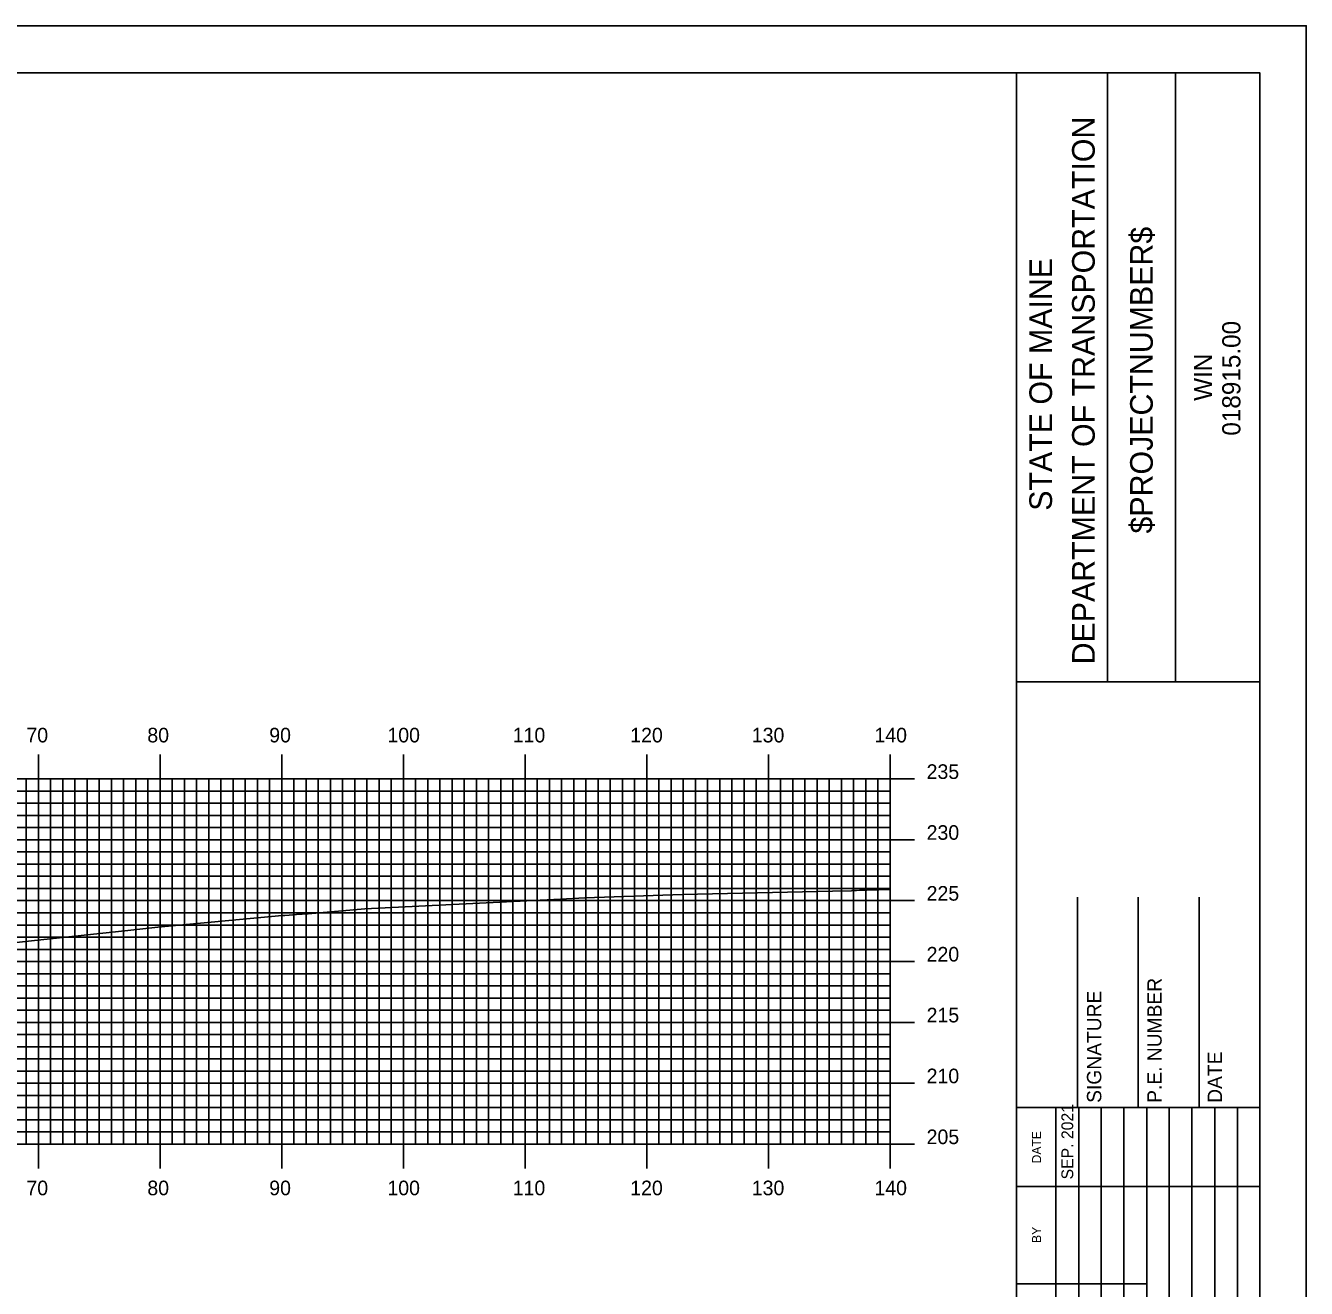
# Model space of a CAD drawing. Extents: x 851348 to 851692, y 364785 to 365005.
# Drawn here: x 851583.1 to 851688.4, y 364901.4 to 365005.1 of the extents above; entities that cross this region are included whole.
import ezdxf

# ---------------------------------------------------------------- set-up
doc = ezdxf.new("R2010")
doc.units = 0
for name, color, linetype in [('BORDER', 7, 'Continuous'), ('H_V ANNOTATION', 7, 'Continuous'), ('MAJOR', 7, 'Continuous'), ('MINOR', 7, 'Continuous'), ('PLOT BOUNDARY', 7, 'Continuous'), ('S_Roadway_Centerline', 7, 'Continuous')]:
    doc.layers.add(name, color=color, linetype=linetype)

msp = doc.modelspace()

# ---------------------------------------------------------------- linework, layer by layer
at = {"layer": 'BORDER'}
for p, q in [((851664.59, 364791.23), (851664.59, 365001.23)), ((851672.05, 364951.23), (851672.05, 365001.23)), ((851677.64, 364951.23), (851677.64, 365001.23)), ((851664.59, 364951.22), (851684.59, 364951.22)), ((851669.59, 364916.24), (851669.59, 364933.53)), ((851674.59, 364916.24), (851674.59, 364933.53)), ((851679.59, 364916.24), (851679.59, 364933.53)), ((851664.59, 364916.24), (851684.59, 364916.24))]:
    msp.add_line(p, q, dxfattribs=at)
msp.add_lwpolyline([(851364.59, 364791.23), (851684.59, 364791.23), (851684.59, 365001.23), (851364.59, 365001.23)], close=True, dxfattribs=at)
for points in [[(851667.82, 364909.74), (851667.82, 364916.24)], [(851669.69, 364881.24), (851669.69, 364916.24)], [(851671.55, 364916.24), (851671.55, 364881.24)], [(851673.41, 364881.24), (851673.41, 364916.24)], [(851675.28, 364881.24), (851675.28, 364916.24)], [(851677.14, 364881.24), (851677.14, 364916.24)], [(851679, 364881.24), (851679, 364916.24)], [(851680.87, 364881.24), (851680.87, 364916.24)], [(851682.73, 364881.24), (851682.73, 364916.24)], [(851667.82, 364881.24), (851667.82, 364914.83)], [(851664.59, 364909.74), (851684.59, 364909.74)], [(851664.59, 364901.74), (851667.82, 364901.74)], [(851667.82, 364901.74), (851675.27, 364901.74)]]:
    msp.add_lwpolyline(points, dxfattribs=at)
at = {"layer": 'MAJOR'}
for p, q in [((851584.19, 364945.24), (851584.19, 364943.23)), ((851594.19, 364945.24), (851594.19, 364943.23)), ((851604.19, 364945.24), (851604.19, 364943.23)), ((851614.19, 364945.24), (851614.19, 364943.23)), ((851624.19, 364945.24), (851624.19, 364943.23)), ((851634.19, 364945.24), (851634.19, 364943.23)), ((851644.19, 364945.24), (851644.19, 364943.23)), ((851654.19, 364945.24), (851654.19, 364943.23)), ((851514.19, 364943.23), (851654.19, 364943.23)), ((851514.19, 364943.23), (851654.19, 364943.23)), ((851584.19, 364913.23), (851584.19, 364943.23)), ((851594.19, 364913.23), (851594.19, 364943.23)), ((851604.19, 364913.23), (851604.19, 364943.23)), ((851614.19, 364913.23), (851614.19, 364943.23)), ((851624.19, 364913.23), (851624.19, 364943.23)), ((851634.19, 364913.23), (851634.19, 364943.23)), ((851644.19, 364913.23), (851644.19, 364943.23)), ((851656.2, 364943.23), (851652.19, 364943.23)), ((851654.19, 364913.23), (851654.19, 364943.23)), ((851654.19, 364913.23), (851654.19, 364943.23)), ((851514.19, 364938.23), (851654.19, 364938.23)), ((851656.2, 364938.23), (851652.19, 364938.23)), ((851514.19, 364933.23), (851654.19, 364933.23)), ((851656.2, 364933.23), (851652.19, 364933.23)), ((851514.19, 364928.23), (851654.19, 364928.23)), ((851656.2, 364928.23), (851652.19, 364928.23)), ((851514.19, 364923.23), (851654.19, 364923.23)), ((851656.2, 364923.23), (851652.19, 364923.23)), ((851514.19, 364918.23), (851654.19, 364918.23)), ((851656.2, 364918.23), (851652.19, 364918.23)), ((851514.19, 364913.23), (851654.19, 364913.23)), ((851514.19, 364913.23), (851654.19, 364913.23)), ((851584.19, 364911.23), (851584.19, 364913.23)), ((851594.19, 364911.23), (851594.19, 364913.23)), ((851604.19, 364911.23), (851604.19, 364913.23)), ((851614.19, 364911.23), (851614.19, 364913.23)), ((851624.19, 364911.23), (851624.19, 364913.23)), ((851634.19, 364911.23), (851634.19, 364913.23)), ((851644.19, 364911.23), (851644.19, 364913.23)), ((851656.2, 364913.23), (851652.19, 364913.23)), ((851654.19, 364911.23), (851654.19, 364913.23))]:
    msp.add_line(p, q, dxfattribs=at)
at = {"layer": 'MINOR'}
for p, q in [((851583.19, 364913.23), (851583.19, 364943.23)), ((851585.19, 364913.23), (851585.19, 364943.23)), ((851586.19, 364913.23), (851586.19, 364943.23)), ((851587.19, 364913.23), (851587.19, 364943.23)), ((851588.19, 364913.23), (851588.19, 364943.23)), ((851589.19, 364913.23), (851589.19, 364943.23)), ((851590.19, 364913.23), (851590.19, 364943.23)), ((851591.19, 364913.23), (851591.19, 364943.23)), ((851592.19, 364913.23), (851592.19, 364943.23)), ((851593.19, 364913.23), (851593.19, 364943.23)), ((851595.19, 364913.23), (851595.19, 364943.23)), ((851596.19, 364913.23), (851596.19, 364943.23)), ((851597.19, 364913.23), (851597.19, 364943.23)), ((851598.19, 364913.23), (851598.19, 364943.23)), ((851599.19, 364913.23), (851599.19, 364943.23)), ((851600.19, 364913.23), (851600.19, 364943.23)), ((851601.19, 364913.23), (851601.19, 364943.23)), ((851602.19, 364913.23), (851602.19, 364943.23)), ((851603.19, 364913.23), (851603.19, 364943.23)), ((851605.19, 364913.23), (851605.19, 364943.23)), ((851606.19, 364913.23), (851606.19, 364943.23)), ((851607.19, 364913.23), (851607.19, 364943.23)), ((851608.19, 364913.23), (851608.19, 364943.23)), ((851609.19, 364913.23), (851609.19, 364943.23)), ((851610.19, 364913.23), (851610.19, 364943.23)), ((851611.19, 364913.23), (851611.19, 364943.23)), ((851612.19, 364913.23), (851612.19, 364943.23)), ((851613.19, 364913.23), (851613.19, 364943.23)), ((851615.19, 364913.23), (851615.19, 364943.23)), ((851616.19, 364913.23), (851616.19, 364943.23)), ((851617.19, 364913.23), (851617.19, 364943.23)), ((851618.19, 364913.23), (851618.19, 364943.23)), ((851619.19, 364913.23), (851619.19, 364943.23)), ((851620.19, 364913.23), (851620.19, 364943.23)), ((851621.19, 364913.23), (851621.19, 364943.23)), ((851622.19, 364913.23), (851622.19, 364943.23)), ((851623.19, 364913.23), (851623.19, 364943.23)), ((851625.19, 364913.23), (851625.19, 364943.23)), ((851626.19, 364913.23), (851626.19, 364943.23)), ((851627.19, 364913.23), (851627.19, 364943.23)), ((851628.19, 364913.23), (851628.19, 364943.23)), ((851629.19, 364913.23), (851629.19, 364943.23)), ((851630.19, 364913.23), (851630.19, 364943.23)), ((851631.19, 364913.23), (851631.19, 364943.23)), ((851632.19, 364913.23), (851632.19, 364943.23)), ((851633.19, 364913.23), (851633.19, 364943.23)), ((851635.19, 364913.23), (851635.19, 364943.23)), ((851636.19, 364913.23), (851636.19, 364943.23)), ((851637.19, 364913.23), (851637.19, 364943.23)), ((851638.19, 364913.23), (851638.19, 364943.23)), ((851639.19, 364913.23), (851639.19, 364943.23)), ((851640.19, 364913.23), (851640.19, 364943.23)), ((851641.19, 364913.23), (851641.19, 364943.23)), ((851642.19, 364913.23), (851642.19, 364943.23)), ((851643.19, 364913.23), (851643.19, 364943.23)), ((851645.19, 364913.23), (851645.19, 364943.23)), ((851646.19, 364913.23), (851646.19, 364943.23)), ((851647.19, 364913.23), (851647.19, 364943.23)), ((851648.19, 364913.23), (851648.19, 364943.23)), ((851649.19, 364913.23), (851649.19, 364943.23)), ((851650.19, 364913.23), (851650.19, 364943.23)), ((851651.19, 364913.23), (851651.19, 364943.23)), ((851652.19, 364913.23), (851652.19, 364943.23)), ((851653.19, 364913.23), (851653.19, 364943.23)), ((851514.19, 364942.23), (851654.19, 364942.23)), ((851654.19, 364942.23), (851652.19, 364942.23)), ((851514.19, 364941.23), (851654.19, 364941.23)), ((851654.19, 364941.23), (851652.19, 364941.23)), ((851514.19, 364940.23), (851654.19, 364940.23)), ((851654.19, 364940.23), (851652.19, 364940.23)), ((851514.19, 364939.23), (851654.19, 364939.23)), ((851654.19, 364939.23), (851652.19, 364939.23)), ((851514.19, 364937.23), (851654.19, 364937.23)), ((851654.19, 364937.23), (851652.19, 364937.23)), ((851514.19, 364936.23), (851654.19, 364936.23)), ((851654.19, 364936.23), (851652.19, 364936.23)), ((851514.19, 364935.23), (851654.19, 364935.23)), ((851654.19, 364935.23), (851652.19, 364935.23)), ((851514.19, 364934.23), (851654.19, 364934.23)), ((851654.19, 364934.23), (851652.19, 364934.23)), ((851514.19, 364932.23), (851654.19, 364932.23)), ((851654.19, 364932.23), (851652.19, 364932.23)), ((851514.19, 364931.23), (851654.19, 364931.23)), ((851654.19, 364931.23), (851652.19, 364931.23)), ((851514.19, 364930.23), (851654.19, 364930.23)), ((851654.19, 364930.23), (851652.19, 364930.23)), ((851514.19, 364929.23), (851654.19, 364929.23)), ((851654.19, 364929.23), (851652.19, 364929.23)), ((851514.19, 364927.23), (851654.19, 364927.23)), ((851654.19, 364927.23), (851652.19, 364927.23)), ((851514.19, 364926.23), (851654.19, 364926.23)), ((851654.19, 364926.23), (851652.19, 364926.23)), ((851514.19, 364925.23), (851654.19, 364925.23)), ((851654.19, 364925.23), (851652.19, 364925.23)), ((851514.19, 364924.23), (851654.19, 364924.23)), ((851654.19, 364924.23), (851652.19, 364924.23)), ((851514.19, 364922.23), (851654.19, 364922.23)), ((851654.19, 364922.23), (851652.19, 364922.23)), ((851514.19, 364921.23), (851654.19, 364921.23)), ((851654.19, 364921.23), (851652.19, 364921.23)), ((851514.19, 364920.23), (851654.19, 364920.23)), ((851654.19, 364920.23), (851652.19, 364920.23)), ((851514.19, 364919.23), (851654.19, 364919.23)), ((851654.19, 364919.23), (851652.19, 364919.23)), ((851514.19, 364917.23), (851654.19, 364917.23)), ((851654.19, 364917.23), (851652.19, 364917.23)), ((851514.19, 364916.23), (851654.19, 364916.23)), ((851654.19, 364916.23), (851652.19, 364916.23)), ((851514.19, 364915.23), (851654.19, 364915.23)), ((851654.19, 364915.23), (851652.19, 364915.23)), ((851514.19, 364914.23), (851654.19, 364914.23)), ((851654.19, 364914.23), (851652.19, 364914.23))]:
    msp.add_line(p, q, dxfattribs=at)
at = {"layer": 'PLOT BOUNDARY'}
msp.add_lwpolyline([(851348.4, 364785.11), (851688.4, 364785.11), (851688.4, 365005.11), (851348.4, 365005.11)], close=True, dxfattribs=at)
at = {"layer": 'S_Roadway_Centerline'}
msp.add_lwpolyline([(851582.15, 364929.76), (851583.61, 364929.92), (851591.55, 364930.78), (851594, 364931.04), (851604.21, 364932), (851604.44, 364932.02), (851604.81, 364932.05), (851605.4, 364932.09), (851606.37, 364932.16), (851611.02, 364932.55), (851627.11, 364933.36), (851629.11, 364933.46), (851637.12, 364933.73), (851649.45, 364934.01), (851651.03, 364934.05), (851651.05, 364934.06), (851651.42, 364934.07), (851651.67, 364934.08), (851651.97, 364934.09), (851652.29, 364934.1), (851653.26, 364934.12), (851654.19, 364934.15)], dxfattribs=at)

# ---------------------------------------------------------------- texts
at = {"layer": 'BORDER'}
for s, height, p in [('DEPARTMENT OF TRANSPORTATION', 1.8635, (851671.01, 364952.64)), ('$PROJECTNUMBER$', 1.8635, (851675.78, 364963.39)), ('STATE OF MAINE', 1.8635, (851667.5, 364965.26)), ('018915.00', 1.491, (851682.98, 364971.43)), ('WIN', 1.491, (851680.66, 364974.29)), ('P.E. NUMBER', 1.1811, (851676.51, 364916.62)), ('SIGNATURE', 1.181, (851671.55, 364916.62)), ('DATE', 1.181, (851681.47, 364916.62)), ('SEP. 2021', 0.969, (851669.24, 364910.33)), ('DATE', 0.743, (851666.6, 364911.65)), ('BY', 0.743, (851666.6, 364905.11))]:
    msp.add_text(s, height=height, rotation=90, dxfattribs=at).set_placement(p)
at = {"layer": 'H_V ANNOTATION'}
for s, p in [('70', (851583.2, 364946.23)), ('80', (851593.14, 364946.23)), ('90', (851603.16, 364946.23)), ('100', (851612.87, 364946.23)), ('110', (851623.17, 364946.23)), ('120', (851632.83, 364946.23)), ('130', (851642.82, 364946.23)), ('140', (851652.9, 364946.23)), ('235', (851657.19, 364943.23)), ('230', (851657.19, 364938.23)), ('225', (851657.19, 364933.23)), ('220', (851657.19, 364928.23)), ('215', (851657.19, 364923.23)), ('210', (851657.19, 364918.23)), ('205', (851657.19, 364913.23)), ('70', (851583.2, 364909.03)), ('80', (851593.14, 364909.03)), ('90', (851603.16, 364909.03)), ('100', (851612.87, 364909.03)), ('110', (851623.17, 364909.03)), ('120', (851632.83, 364909.03)), ('130', (851642.82, 364909.03)), ('140', (851652.9, 364909.03))]:
    msp.add_text(s, height=1.2, dxfattribs=at).set_placement(p)

doc.saveas('drawing.dxf')
